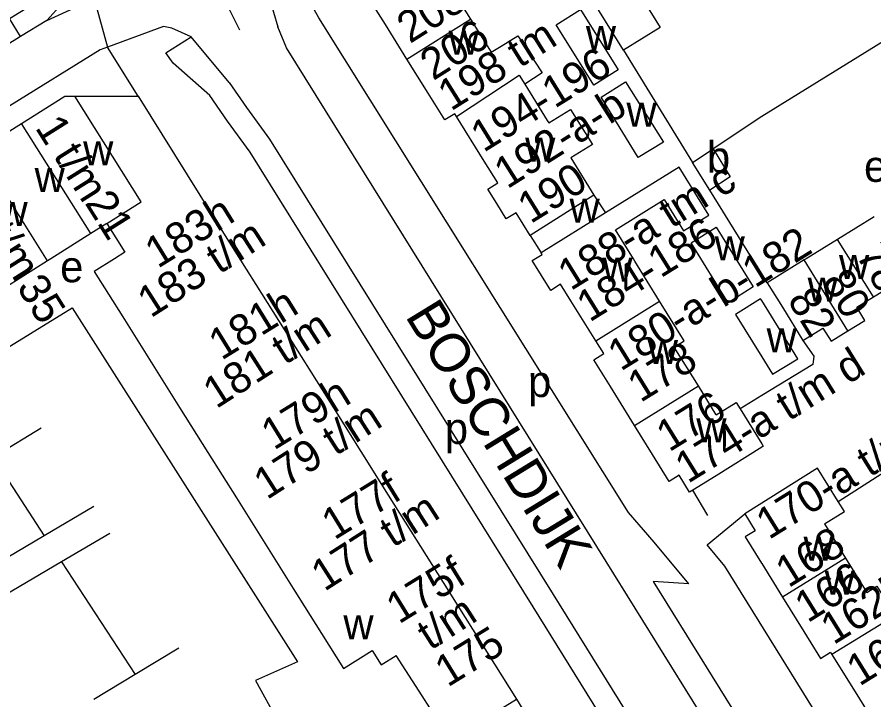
# Model space of a CAD drawing. Extents: x 159902 to 161769, y 383692 to 384875.
# Drawn here: x 160604.7 to 160714.3, y 384243.6 to 384330.9 of the extents above; entities that cross this region are included whole.
import ezdxf

# ---------------------------------------------------------------- set-up
doc = ezdxf.new("R2010")
doc.units = 0
for name, color, linetype in [('BLT_Basislijn', 7, 'Continuous'), ('BLT_Bebouwing', 7, 'Continuous'), ('BLT_Centroide', 7, 'Continuous'), ('BLT_Huisnummer', 7, 'Continuous'), ('BLT_Huisnummer_ tussenligend', 7, 'Continuous'), ('BLT_Huisnummer_reeks', 7, 'Continuous'), ('BLT_Onderdoorgang_en_onderverdeling', 7, 'Continuous'), ('BLT_Onderverdeling_panden', 7, 'Continuous'), ('BLT_Straatnaam', 7, 'Continuous'), ('BLT_Vlakafsluiter', 7, 'Continuous')]:
    doc.layers.add(name, color=color, linetype=linetype)

msp = doc.modelspace()

# ---------------------------------------------------------------- linework, layer by layer
at = {"layer": 'BLT_Basislijn'}
for p, q in [((160636.68, 384334.42), (160638.08, 384329.66)), ((160608.54, 384330.46), (160614.59, 384333.31)), ((160608.54, 384330.46), (160605.16, 384328.43)), ((160631.85, 384322.57), (160627.02, 384328.39)), ((160620.21, 384320.79), (160616.32, 384327.07)), ((160682.31, 384326.7), (160691.15, 384312.3)), ((160700, 384318.21), (160693.77, 384314.05)), ((160709.79, 384268.96), (160731.73, 384283.05)), ((160700, 384282.5), (160697.24, 384280.81)), ((160607.82, 384278.35), (160601.67, 384274.6)), ((160601.67, 384274.6), (160608.22, 384264.58)), ((160693.12, 384267.18), (160691.2, 384270.43)), ((160614.57, 384268.33), (160608.22, 384264.58)), ((160608.22, 384264.58), (160601.11, 384260.38)), ((160616.6, 384264.88), (160610.42, 384261.23)), ((160610.42, 384261.23), (160603.14, 384256.94)), ((160610.42, 384261.23), (160619.84, 384246.83)), ((160625.42, 384250.2), (160619.84, 384246.83)), ((160619.84, 384246.83), (160614.55, 384243.64)), ((160635.26, 384246.06), (160638.17, 384240.79))]:
    msp.add_line(p, q, dxfattribs=at)
for points in [[(160621.83, 384346.99), (160625.43, 384342.73), (160631.02, 384333.68), (160633.19, 384329.27)], [(160610.43, 384336.68), (160610.68, 384335.23), (160610.56, 384332.7), (160608.54, 384330.46)], [(160690.65, 384258.45), (160686.25, 384263.77), (160682.97, 384267.55), (160643.33, 384330.83), (160640.14, 384336.58)], [(160627.02, 384328.39), (160624.54, 384329.51), (160623.46, 384329.72), (160616.32, 384327.07)], [(160699.52, 384231.92), (160694.92, 384237.43), (160680.1, 384261.29), (160639.19, 384326.99), (160638.08, 384329.66)], [(160718.71, 384329.18), (160717, 384328.68), (160700, 384318.21)], [(160690.59, 384226.39), (160689.56, 384225.7), (160688.74, 384225.37), (160687.85, 384225.32), (160686.71, 384225.7), (160685.84, 384226.52), (160682.63, 384233.03), (160681.76, 384236.03), (160680.62, 384239.33), (160679.98, 384240.64), (160670.76, 384255.48), (160634.55, 384313.64), (160631.64, 384317.6), (160629.38, 384320.87), (160624.71, 384325.04), (160623.77, 384326.36), (160627.02, 384328.39)], [(160616.32, 384327.07), (160615.38, 384326.72), (160592.21, 384312.4)], [(160631.85, 384322.57), (160634.08, 384319.34), (160637.04, 384315.32), (160673.31, 384257.06), (160682.6, 384242.1), (160685.8, 384235.62), (160688.95, 384229), (160690.59, 384226.39)], [(160700.71, 384296.92), (160693.35, 384308.8)], [(160597.5, 384292.73), (160601.09, 384287.15), (160611.79, 384293.71), (160640.61, 384248.47), (160635.26, 384246.06)], [(160705.27, 384289.54), (160706.66, 384287.54), (160706.52, 384286.48), (160700, 384282.5)], [(160741.07, 384190.08), (160739.68, 384189.17), (160695.29, 384260.67), (160693.02, 384263.42), (160697.82, 384267.39)], [(160690.65, 384258.45), (160686.09, 384258.71), (160699.66, 384236.9), (160704.7, 384236.03)]]:
    msp.add_lwpolyline(points, dxfattribs=at)
at = {"layer": 'BLT_Bebouwing'}
for p, q in [((160660.06, 384334.97), (160662.76, 384330.63)), ((160673.68, 384329.94), (160676.81, 384331.9)), ((160676.81, 384331.9), (160681.62, 384324.16)), ((160654.59, 384325.55), (160651.85, 384329.95)), ((160662.76, 384330.63), (160665.39, 384326.41)), ((160678.5, 384322.21), (160673.68, 384329.94)), ((160657.32, 384321.17), (160654.59, 384325.55)), ((160681.62, 384324.16), (160678.5, 384322.21)), ((160669.69, 384322.34), (160672.57, 384317.71)), ((160679.46, 384320.68), (160682.59, 384322.64)), ((160682.59, 384322.64), (160687.41, 384314.92)), ((160612.11, 384320.8), (160620.21, 384320.79)), ((160684.18, 384312.94), (160679.46, 384320.68)), ((160664.51, 384312.47), (160660.93, 384318.22)), ((160687.41, 384314.92), (160684.18, 384312.94)), ((160691.15, 384312.3), (160693.77, 384314.05)), ((160675.56, 384312.91), (160678.53, 384308.13)), ((160693.35, 384308.8), (160691.15, 384312.3)), ((160714.38, 384305.38), (160709.7, 384302.49)), ((160616.2, 384304.51), (160614.18, 384303.24)), ((160690.95, 384302.04), (160694.18, 384304.04)), ((160694.18, 384304.04), (160698.91, 384296.4)), ((160670.39, 384302.99), (160671.78, 384300.76)), ((160695.7, 384294.39), (160690.95, 384302.04)), ((160709.7, 384302.49), (160705.68, 384300)), ((160608.65, 384299.76), (160603.37, 384296.43)), ((160683.76, 384299.7), (160683.58, 384300)), ((160686.93, 384294.6), (160683.76, 384299.7)), ((160705.44, 384299.85), (160700.71, 384296.92)), ((160705.68, 384300), (160705.44, 384299.85)), ((160714.31, 384295.13), (160719.05, 384298.04)), ((160698.91, 384296.4), (160695.7, 384294.39)), ((160678.76, 384289.52), (160675.58, 384294.64)), ((160618.26, 384292.57), (160621.89, 384286.78)), ((160691.89, 384283.75), (160688.81, 384288.72)), ((160621.89, 384286.78), (160625.52, 384280.99)), ((160683.72, 384278.68), (160680.64, 384283.65)), ((160694.18, 384280.05), (160691.89, 384283.75)), ((160625.52, 384280.99), (160629.16, 384275.21)), ((160697.24, 384280.81), (160700, 384276.34)), ((160686.01, 384274.99), (160683.72, 384278.68)), ((160629.16, 384275.21), (160632.79, 384269.42)), ((160691.2, 384270.43), (160690.76, 384270.16)), ((160632.79, 384269.42), (160636.42, 384263.64)), ((160708.02, 384266.09), (160710.73, 384261.72)), ((160636.42, 384263.64), (160640.05, 384257.85)), ((160699.95, 384261.09), (160700, 384261.01)), ((160700, 384261.01), (160702.64, 384256.74)), ((160710.73, 384261.72), (160713.44, 384257.34)), ((160640.05, 384257.85), (160643.68, 384252.07)), ((160702.64, 384256.74), (160705.37, 384252.34)), ((160656.56, 384244.09), (160653.23, 384249.26)), ((160708.98, 384249.38), (160712.5, 384243.7)), ((160660.18, 384238.49), (160656.56, 384244.09)), ((160668.61, 384243.69), (160671.86, 384238.51))]:
    msp.add_line(p, q, dxfattribs=at)
for points in [[(160605.16, 384328.43), (160603.75, 384330.72), (160608.27, 384333.57), (160606.77, 384335.97), (160609.76, 384337.83)], [(160682.31, 384326.7), (160678.49, 384332.85), (160675.85, 384337.1)], [(160651.85, 384329.95), (160649.76, 384333.29), (160651.04, 384334.09), (160649.69, 384336.24)], [(160685.13, 384332.62), (160686.99, 384329.6), (160682.31, 384326.7)], [(160605.16, 384328.43), (160604.69, 384328.15), (160595.04, 384322.18)], [(160665.39, 384326.41), (160666.66, 384327.21), (160668.8, 384328.54), (160671.91, 384323.8), (160669.69, 384322.34)], [(160605.31, 384317.32), (160610.86, 384320.81), (160612.11, 384320.8)], [(160620.21, 384320.79), (160631.15, 384303.26), (160638.19, 384292.13), (160645.21, 384280.95), (160652.19, 384269.77), (160659.23, 384258.59), (160668.61, 384243.69)], [(160660.93, 384318.22), (160660.72, 384318.55), (160659.45, 384317.76), (160657.32, 384321.17)], [(160672.57, 384317.71), (160672.77, 384317.39), (160675.55, 384319.11), (160678.34, 384314.63), (160675.56, 384312.91)], [(160599.78, 384313.85), (160605.31, 384317.32)], [(160693.77, 384314.05), (160695.95, 384310.48), (160693.35, 384308.8)], [(160666.09, 384307.07), (160664.95, 384308.92), (160666.22, 384309.71), (160664.51, 384312.47)], [(160683.58, 384300), (160681.28, 384303.71), (160687.51, 384307.57), (160689.99, 384303.57), (160693.23, 384305.58), (160689.42, 384311.73), (160679.99, 384305.86)], [(160678.53, 384308.13), (160679.99, 384305.86)], [(160670.39, 384302.99), (160668.59, 384305.89), (160667.31, 384305.1), (160666.09, 384307.07)], [(160616.2, 384304.51), (160618.52, 384300.83), (160617.21, 384300), (160614.62, 384298.37), (160618.26, 384292.57)], [(160614.18, 384303.24), (160609.04, 384300), (160608.65, 384299.76)], [(160670.63, 384299.77), (160671.9, 384300.56), (160671.78, 384300.76)], [(160675.58, 384294.64), (160674.27, 384296.74), (160673, 384295.95), (160670.63, 384299.77)], [(160700.71, 384296.92), (160702.64, 384293.8), (160705.27, 384289.54)], [(160711.02, 384290.77), (160713.17, 384292.1), (160712.15, 384293.81), (160714.31, 384295.13)], [(160688.81, 384288.72), (160690.08, 384289.51), (160686.93, 384294.6)], [(160700, 384294.65), (160699.86, 384294.87), (160696.65, 384292.86), (160700, 384287.46)], [(160700, 384287.46), (160701.38, 384285.24), (160704.6, 384287.22), (160700, 384294.65)], [(160705.27, 384289.54), (160707.83, 384291.12), (160708.87, 384289.45), (160711.02, 384290.77)], [(160680.64, 384283.65), (160678.51, 384287.08), (160679.78, 384287.87), (160678.76, 384289.52)], [(160694.18, 384280.05), (160696.74, 384281.61), (160697.24, 384280.81)], [(160700, 384276.34), (160700.18, 384276.05), (160700, 384275.93)], [(160700, 384275.93), (160694.17, 384272.26), (160691.2, 384270.43)], [(160690.76, 384270.16), (160689.43, 384272.32), (160688.16, 384271.53), (160686.01, 384274.99)], [(160709.79, 384268.96), (160707.14, 384273.24), (160697.82, 384267.39)], [(160708.02, 384266.09), (160710.59, 384267.68), (160709.79, 384268.96)], [(160697.82, 384267.39), (160699.16, 384265.22), (160697.88, 384264.43), (160699.95, 384261.09)], [(160713.44, 384257.34), (160714.74, 384258.15), (160717.07, 384254.39)], [(160705.37, 384252.34), (160707.52, 384248.88), (160708.8, 384249.67), (160708.98, 384249.38)], [(160643.68, 384252.07), (160646.49, 384247.6), (160650.15, 384249.9), (160651.31, 384248.05), (160653.23, 384249.26)], [(160712.51, 384243.7), (160714.16, 384241.04), (160712.88, 384240.25), (160714.16, 384238.2)]]:
    msp.add_lwpolyline(points, dxfattribs=at)
at = {"layer": 'BLT_Onderdoorgang_en_onderverdeling'}
for p, q in [((160678.53, 384308.13), (160670.39, 384302.99)), ((160679.99, 384305.86), (160671.78, 384300.76))]:
    msp.add_line(p, q, dxfattribs=at)
at = {"layer": 'BLT_Onderverdeling_panden'}
for p, q in [((160654.59, 384325.55), (160662.76, 384330.63)), ((160620.62, 384307.29), (160612.11, 384320.8)), ((160614.18, 384303.24), (160605.31, 384317.32)), ((160608.65, 384299.76), (160599.78, 384313.85)), ((160616.2, 384304.51), (160620.62, 384307.29)), ((160714.31, 384295.13), (160709.7, 384302.49)), ((160711.02, 384290.77), (160705.44, 384299.85)), ((160678.76, 384289.52), (160686.93, 384294.6)), ((160683.72, 384278.68), (160691.89, 384283.75)), ((160700, 384261.12), (160699.95, 384261.09)), ((160710.73, 384261.72), (160702.64, 384256.74)), ((160717.07, 384254.39), (160708.98, 384249.38)), ((160664.4, 384241.09), (160668.61, 384243.69))]:
    msp.add_line(p, q, dxfattribs=at)
msp.add_lwpolyline([(160660.93, 384318.22), (160668.97, 384323.5), (160669.69, 384322.34)], dxfattribs=at)
at = {"layer": 'BLT_Vlakafsluiter'}
msp.add_line((160614.59, 384333.31), (160616.32, 384327.07), dxfattribs=at)

# ---------------------------------------------------------------- texts
at = {"layer": 'BLT_Centroide'}
for s, p in [('w', (160659.95, 384326.09)), ('w', (160677.5, 384326.72)), ('w', (160682.7, 384316.89)), ('w', (160613.19, 384311.95)), ('w', (160669.73, 384312.41)), ('b', (160692.98, 384311.02)), ('e', (160713.08, 384309.84)), ('w', (160606.98, 384308.55)), ('w', (160602.23, 384304.19)), ('w', (160675.41, 384304.63)), ('w', (160693.97, 384299.81)), ('w', (160709.88, 384297.41)), ('e', (160610.25, 384297)), ('w', (160679.61, 384297.09)), ('w', (160705.86, 384294.53)), ('w', (160700.62, 384288.05)), ('w', (160685.42, 384286.53)), ('p', (160670.1, 384282.32)), ('w', (160691.63, 384276.51)), ('p', (160659.45, 384276.31)), ('w', (160705.34, 384261.41)), ('w', (160708.05, 384257.03)), ('w', (160646.48, 384251.32))]:
    msp.add_text(s, height=4, dxfattribs=at).set_placement(p)
at = {"layer": 'BLT_Huisnummer'}
msp.add_text('82', height=4, rotation=301.6667, dxfattribs=at).set_placement((160703.2, 384294.74))
at = {"layer": 'BLT_Huisnummer_ tussenligend'}
for s, p in [('78', (160711.96, 384300.48)), ('80', (160707.62, 384297.1))]:
    msp.add_text(s, height=4, rotation=301.5716, dxfattribs=at).set_placement(p)
at = {"layer": 'BLT_Huisnummer_reeks'}
for s, rotation, p in [('187 01', 31.6119, (160595.97, 384328.79)), ('208', 32.2823, (160654.99, 384327.46)), ('206', 32.2823, (160657.97, 384322.72)), ('198 tm', 32.085, (160660.23, 384318.82)), ('194-196', 31.7942, (160664.41, 384313.53)), ('192-a-b', 32.2823, (160667.44, 384308.86)), ('1', 302.1864, (160606.97, 384316.77)), ('t/m', 302.1957, (160609.3, 384313.22)), ('190', 31.7942, (160670.42, 384304.41)), ('188-a tm c', 31.7942, (160675.56, 384295.84)), ('21', 302.1864, (160613.32, 384307.15)), ('183h', 31.6664, (160622.73, 384298.7)), ('t/m', 302.1957, (160600.64, 384303.18)), ('184-186', 31.8823, (160677.97, 384291.82)), ('183 t/m', 32.6029, (160621.83, 384292.36)), ('180-a-b-182', 31.7954, (160681.95, 384285.55)), ('35', 302.1864, (160604.61, 384296.39)), ('181h', 31.6664, (160630.88, 384286.94)), ('181 t/m', 32.6029, (160630.22, 384280.75)), ('178', 31.7922, (160684.48, 384281.54)), ('174-a t/m d', 31.7941, (160690.55, 384271.19)), ('170-a t/m c-172', 31.7898, (160700.91, 384264.01)), ('179h', 31.6664, (160637.6, 384275.45)), ('176', 31.7922, (160688.15, 384275.22)), ('179 t/m', 32.6029, (160636.7, 384269.11)), ('177f', 31.6664, (160645.33, 384263.96)), ('162b-164-a-b', 31.7955, (160709.18, 384250.56)), ('177 t/m', 32.6029, (160644.05, 384257.38)), ('168', 31.7974, (160703.41, 384257.84)), ('175f', 31.6664, (160653.58, 384253.21)), ('166', 31.798, (160705.86, 384253.36)), ('t/m', 32.6029, (160657.6, 384249.85)), ('162-a', 31.798, (160712.49, 384245.26)), ('175', 31.6664, (160659.82, 384245.14))]:
    msp.add_text(s, height=4, rotation=rotation, dxfattribs=at).set_placement(p)
at = {"layer": 'BLT_Straatnaam'}
msp.add_text('BOSCHDIJK', height=5, rotation=301.4898, dxfattribs=at).set_placement((160654.31, 384292.69))

doc.saveas('drawing.dxf')
